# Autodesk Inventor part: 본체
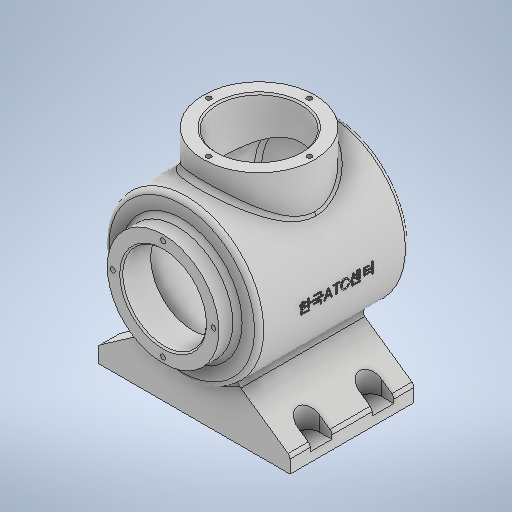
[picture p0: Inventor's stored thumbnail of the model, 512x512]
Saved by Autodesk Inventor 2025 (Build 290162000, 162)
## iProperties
Created: 2024-07
Part Number: 본체
Material: 일반
Document SubType Name: Modeling
Designer: admin
Density: 1 g/cm^3
Appearance: 기본값
Author: admin
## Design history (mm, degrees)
sketch "스케치3"
  geometry: L1 (0, 54)-(-50, 54); L2 (-50, 54)-(-50, -42.336); L3 (0, -54)-(0, 54); A1 r 113 centre (0, 59) between (-50, -42.336) and (50, -42.336); 3 further points
  constraints: 6 end point, 4 point on circle, 2 midpoint, 1 centre point, 1 coincident, 1 horizontal, 1 horizontal alignment, 1 parallel, 1 perpendicular, 1 vertical alignment
  dimensions: "d3" = 50 distance of L1.start L1.end; "d10" = 113 radius of A1; "d11" = 108 distance from line of L3.start L1
revolve "회전1" sketch "스케치3" stored, may be unused: angle "d8" = 90 deg
fillet "모깎기1" dims "d12" = 3
feature "쉘1" dims "d13" = 7
sketch "스케치4"
  geometry: C1 r 36 at (0, 0); 1 further point
  constraints: 1 centre point, 1 coincident
  dimensions: "d14" = 72 diameter of C1
extrude "돌출2" join sketch "스케치4" distance "d15" = 12; taper "d16" = 0 deg
sketch "스케치5"
  geometry: C1 r 36 at (0, 0) reference; 2 further points
  constraints: 1 coincident
hole "구멍1" sketch "스케치5" at (0, 0) diameter "d17" = 54; stored, may be unused: countersink angle "d21" = 90 deg, drill point angle "d23" = 0 deg; dims "d18" = 8, "d19" = 4, "d20" = 2, "d22" = 19
sketch "스케치7"
  geometry: L1 (0, 46.396)-(0, -104.361); L2 (-62, -77)-(62, -77); L3 (62, -77)-(62, -67); L4 (62, -67)-(24.427, -40.691); L5 (-24.427, -40.691)-(-62, -67); L6 (-62, -67)-(-62, -77); A1 r 48.181 centre (0, 0.839) between (-24.427, -40.691) and (24.427, -40.691); 1 further point
  constraints: 12 end point, 2 point on circle, 1 centre point, 1 horizontal, 1 horizontal alignment, 1 parallel, 1 perpendicular, 1 point on line, 1 vertical, 2 other
  dimensions: "d32" = 55 deg angle of L6 L5; "d33" = 10 distance of L5.end L2.start; "d34" = 77 distance from line of point (0, 0) L2; "d36" = 124 distance of L2.start L2.end; "d37" = 48.18065 radius of A1; "d38" = 45.86871 distance of L5.start L5.end
extrude "돌출3" join sketch "스케치7" distance "d39" = 46; taper "d40" = 0 deg; dims "d131" = 34, "d132" = 0
node "작업 평면2"
sketch "스케치9"
  geometry: L1 (-26, 100)-(-98, 100) reference; C1 r 36 at (-62, 38); 2 further points
  constraints: 1 centre point, 1 coincident, 1 midpoint, 1 vertical alignment
  dimensions: "d46" = 72 diameter of C1; "d118" = 62 distance from line of point (-62, 38) L1
extrude "돌출5" join sketch "스케치9" stored distance "d47" = 10; taper "d48" = 0 deg
sketch "스케치10"
  geometry: C1 r 36 at (0, 0) reference; 2 further points
  constraints: 1 coincident
hole "구멍2" sketch "스케치10" at (0, 0) diameter "d49" = 54; stored, may be unused: countersink angle "d53" = 90 deg, drill point angle "d55" = 0 deg; dims "d50" = 6, "d51" = 4, "d52" = 2, "d54" = 40
fillet "모깎기2" dims "d56" = 3
fillet "모깎기4" dims "d74" = 3
fillet "모깎기3" dims "d57" = 3
chamfer "모따기1" distance "d58" = 1; stored, may be unused: second distance "d59" = 2, angle "d60" = 45 deg
sketch "스케치11"
  geometry: L1 (-8, 67)-(0, 67); L2 (0, 0)-(0, 80) reference; L3 (-8, 53)-(0, 53); L4 (-124, 80)-(0, 80) reference; L5 (-135.9, 34)-(24.657, 34); L6 (-62, 72.718)-(-62, -22.908); L7 (-124, 0)-(-124, 80) reference; L8 (-8, 1)-(0, 1); L9 (-8, 15)-(0, 15); L10 (-116, 53)-(-124, 53); L11 (-116, 67)-(-124, 67); L12 (-116, 15)-(-124, 15); L13 (-116, 1)-(-124, 1); A1 r 7 centre (-8, 60) between (-8, 67) and (-8, 53); A2 r 7 centre (-8, 8) between (-8, 15) and (-8, 1); A3 r 7 centre (-116, 60) between (-116, 53) and (-116, 67); A4 r 7 centre (-116, 8) between (-116, 1) and (-116, 15); 9 further points
  constraints: 20 end point, 15 symmetric about line, 8 point on circle, 4 centre point, 4 point on line, 2 horizontal, 1 midpoint, 1 parallel, 1 tangent, 1 vertical, 3 other
  dimensions: "d61" = 14 diameter of A1; "d62" = 14 distance from line of point (-4, 53) L1; "d63" = 20 distance from line of A1.centre L4; "d64" = 8 distance from line of L2 A1.centre
sketch "스케치15" dims "d119" = 65
  geometry: L1 (50, 44.454)-(50, -47) reference; C1 r 36 at (0, 0) reference; 3 further points
  constraints: 2 horizontal alignment, 3 other
hole "구멍3" sketch "스케치15" at (-32.5, 0) diameter "d76" = 3.242; stored, may be unused: countersink angle "d80" = 90 deg, drill point angle "d82" = 118 deg; dims "d77" = 8, "d78" = 4, "d79" = 2, "d81" = 10
fillet "모깎기6" dims "d98" = 3
fillet "모깎기7" dims "d99" = 3
node "작업 평면4"
sketch "스케치19"
  geometry: L1 (36, 66)-(-36, 66) reference; 2 further points
  constraints: 1 vertical alignment, 1 other
  dimensions: "d115" = 62 distance from line of L1 point (0, 4)
feature "엠보싱1" sketch "스케치19" dims "d3" = 50, "d10" = 113, "d11" = 108, "d116" = 0.5, "d117" = 0
sketch "스케치20" dims "d120" = 65
  geometry: 3 further points
  constraints: 2 vertical alignment, 1 coincident, 2 other
hole "구멍7" sketch "스케치20" at (0, 32.5) diameter "d121" = 3.242; stored, may be unused: countersink angle "d125" = 90 deg, drill point angle "d127" = 118 deg; dims "d122" = 8, "d123" = 4, "d124" = 2, "d126" = 10
node "작업 평면5"
sketch "스케치22"
  geometry: L1 (124, -80)-(124, 0) reference; L2 (0, 0)-(124, 0) reference; L3 (116, -13)-(124, -13); L4 (122.721, -80)-(122.721, 0) reference; L5 (116, -27)-(124, -27); L6 (-20.578, -40)-(180.889, -40); L7 (62, 44.885)-(62, -136.998); L8 (116, -53)-(124, -53); L9 (116, -67)-(124, -67); L10 (8, -27)-(0, -27); L11 (8, -13)-(0, -13); L12 (8, -53)-(0, -53); L13 (8, -67)-(0, -67); L14 (0, -80)-(0, 0) reference; A1 r 7 centre (116, -20) between (116, -13) and (116, -27); A2 r 7 centre (116, -60) between (116, -53) and (116, -67); A3 r 7 centre (8, -20) between (8, -27) and (8, -13); A4 r 7 centre (8, -60) between (8, -67) and (8, -53); 3 further points
  constraints: 20 end point, 15 symmetric about line, 8 point on circle, 4 centre point, 2 horizontal, 2 perpendicular, 2 point on line, 2 vertical alignment, 1 tangent, 1 vertical, 3 other
  dimensions: "d134" = 14 diameter of A1; "d135" = 8 distance of L3.start L3.end; "d136" = 20 distance from line of L2 A1.centre; "d137" = 40 distance between parallel lines of L6 L2; "d138" = 62 distance between parallel lines of L1 L7
extrude "돌출9" cut sketch "스케치22" distance "d139" = 19.75; taper "d140" = 0 deg
node "솔리드2"
pattern_circular "원형 패턴1" dims angle "d84" = 360 deg
pattern_circular "원형 패턴3" dims angle "d129" = 360 deg
feature "A9D066F2-1C7D-4E18-AEED-F7BC21143FA4" dims "d17" = 54, "d18" = 8, "d19" = 4, "d20" = 2, "d21" = 90 deg, "d22" = 19, "d23" = 0
other parameters: "d45" = -142, "d114" = 119.75, "d133" = -25.75
